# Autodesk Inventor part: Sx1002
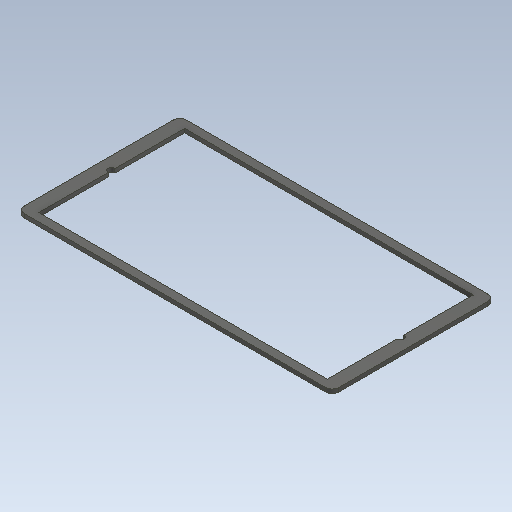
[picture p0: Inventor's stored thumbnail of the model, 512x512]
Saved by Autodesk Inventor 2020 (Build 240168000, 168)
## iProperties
Created: 2021-02
Part Number: Sx1002
Material: Generico
Document SubType Name: Modeling
Designer: zambolin
Density: 1 g/cm^3
Appearance: Default
Author: zambolin
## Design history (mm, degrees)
feature "Solido2"
node "Solido1"
